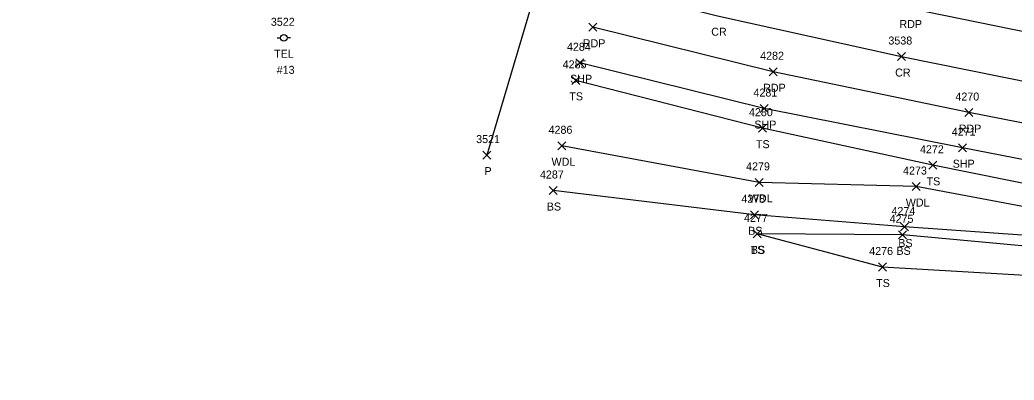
# Model space of a CAD drawing. Extents: x 1647574 to 1652703, y 212895 to 228670.
# Drawn here: x 1648648 to 1648896.4, y 227078.5 to 227168.5 of the extents above; entities that cross this region are included whole.
import ezdxf

# ---------------------------------------------------------------- set-up
doc = ezdxf.new("R2010")
doc.units = 0
for name, color, linetype in [('D_A', 7, 'Continuous'), ('D_I', 7, 'Continuous'), ('D_TIC', 7, 'Continuous'), ('DCP', 7, 'Continuous'), ('L_A', 7, 'Continuous'), ('L_I', 7, 'Continuous'), ('L_TIC', 7, 'Continuous'), ('LAWA', 7, 'Continuous'), ('LELB', 7, 'Continuous'), ('P_A', 7, 'Continuous'), ('P_I', 7, 'Continuous'), ('P_TIC', 7, 'Continuous'), ('PET', 7, 'Continuous'), ('PRC', 7, 'Continuous'), ('PSP', 7, 'Continuous'), ('U_A', 7, 'Continuous'), ('U_C', 7, 'Continuous'), ('U_I', 7, 'Continuous'), ('UP', 7, 'Continuous')]:
    doc.layers.add(name, color=color, linetype=linetype)

msp = doc.modelspace()

# ---------------------------------------------------------------- linework, layer by layer
at = {"layer": 'D_TIC'}
for points in [[(1648763.66, 227133.75), (1648765.66, 227135.75)], [(1648765.66, 227133.75), (1648763.66, 227135.75)]]:
    msp.add_lwpolyline(points, dxfattribs=at)
at = {"layer": 'DCP'}
msp.add_lwpolyline([(1648791.3, 227224.56), (1648764.66, 227134.75)], dxfattribs=at)
at = {"layer": 'L_TIC'}
for points in [[(1648785.83, 227152.43), (1648787.83, 227154.43)], [(1648787.83, 227152.43), (1648785.83, 227154.43)], [(1648832.46, 227140.48), (1648834.46, 227142.48)], [(1648834.46, 227140.48), (1648832.46, 227142.48)], [(1648782.37, 227136.08), (1648784.37, 227138.08)], [(1648784.37, 227136.08), (1648782.37, 227138.08)], [(1648875.09, 227131.2), (1648877.09, 227133.2)], [(1648877.09, 227131.2), (1648875.09, 227133.2)], [(1648831.67, 227126.94), (1648833.67, 227128.94)], [(1648833.67, 227126.94), (1648831.67, 227128.94)], [(1648870.87, 227125.89), (1648872.87, 227127.89)], [(1648872.87, 227125.89), (1648870.87, 227127.89)], [(1648780.16, 227124.9), (1648782.16, 227126.9)], [(1648782.16, 227124.9), (1648780.16, 227126.9)], [(1648830.48, 227118.83), (1648832.48, 227120.83)], [(1648832.48, 227118.83), (1648830.48, 227120.83)], [(1648867.98, 227115.79), (1648869.98, 227117.79)], [(1648869.98, 227115.79), (1648867.98, 227117.79)], [(1648831.14, 227114.07), (1648833.14, 227116.07)], [(1648833.14, 227114.07), (1648831.14, 227116.07)], [(1648831.14, 227114.07), (1648833.14, 227116.07)], [(1648833.14, 227114.07), (1648831.14, 227116.07)], [(1648867.51, 227113.83), (1648869.51, 227115.83)], [(1648869.51, 227113.83), (1648867.51, 227115.83)], [(1648862.48, 227105.79), (1648864.48, 227107.79)], [(1648864.48, 227105.79), (1648862.48, 227107.79)]]:
    msp.add_lwpolyline(points, dxfattribs=at)
at = {"layer": 'LAWA'}
msp.add_lwpolyline([(1649030.64, 227023.85), (1649020.98, 227035.14), (1648998.91, 227050.08), (1648974.89, 227082.83), (1648958.09, 227100.96), (1648932, 227102.73), (1648925.38, 227109.58), (1648919.51, 227113.25), (1648913.13, 227119.19), (1648871.87, 227126.89), (1648832.67, 227127.94), (1648783.37, 227137.08)], dxfattribs=at)
at = {"layer": 'LELB'}
for points in [[(1649303.94, 227051.18), (1649261.07, 227060.39), (1649216.61, 227069.45), (1649178.25, 227076.12), (1649140.52, 227081.32), (1649094.47, 227090.06), (1649051.01, 227097.65), (1649006.72, 227103.93), (1648958.76, 227112.58), (1648914.48, 227124.45), (1648876.09, 227132.2), (1648833.46, 227141.48), (1648786.83, 227153.43)], [(1649303.06, 227047.28), (1649260.98, 227055.31), (1649217.96, 227064.4), (1649177.85, 227072.42), (1649139.31, 227077.28), (1649094.12, 227086.64), (1649050.12, 227095.02), (1649005.65, 227100.61), (1648959.22, 227107.57), (1648919.51, 227113.25), (1648868.98, 227116.79), (1648831.48, 227119.83), (1648781.16, 227125.9)], [(1649302.97, 227044.78), (1649260.67, 227052.98), (1649215.1, 227059.72), (1649174.92, 227066.32), (1649138.43, 227073.45), (1649092.93, 227081.32), (1649048.99, 227090.42), (1649005.13, 227098.96), (1648958.86, 227104.77), (1648925.38, 227109.58), (1648868.51, 227114.83), (1648832.14, 227115.07)], [(1648932, 227102.73), (1648863.48, 227106.79), (1648832.14, 227115.07)]]:
    msp.add_lwpolyline(points, dxfattribs=at)
at = {"layer": 'P_TIC'}
for points in [[(1648790.11, 227165.69), (1648792.11, 227167.69)], [(1648792.11, 227165.69), (1648790.11, 227167.69)], [(1648867.21, 227158.38), (1648869.21, 227160.38)], [(1648869.21, 227158.38), (1648867.21, 227160.38)], [(1648786.9, 227156.82), (1648788.9, 227158.82)], [(1648788.9, 227156.82), (1648786.9, 227158.82)], [(1648835.17, 227154.58), (1648837.17, 227156.58)], [(1648837.17, 227154.58), (1648835.17, 227156.58)], [(1648832.93, 227145.38), (1648834.93, 227147.38)], [(1648834.93, 227145.38), (1648832.93, 227147.38)], [(1648884.03, 227144.38), (1648886.03, 227146.38)], [(1648886.03, 227144.38), (1648884.03, 227146.38)], [(1648882.47, 227135.6), (1648884.47, 227137.6)], [(1648884.47, 227135.6), (1648882.47, 227137.6)]]:
    msp.add_lwpolyline(points, dxfattribs=at)
at = {"layer": 'PET'}
for points in [[(1648582.82, 227256.08), (1648618.15, 227243), (1648661.46, 227228.08), (1648697.31, 227216.44), (1648732, 227205.65), (1648767.28, 227195.85), (1648794.92, 227188.71), (1648824.66, 227181.32), (1648870.23, 227171.5), (1648904.55, 227164.5), (1648941.4, 227157.32), (1648982.59, 227149.56), (1649013.45, 227143.77), (1649051.48, 227136.02), (1649092.56, 227128.28), (1649129.41, 227121.26), (1649164.13, 227114.97), (1649203.07, 227107.32), (1649253.12, 227097.95), (1649285.33, 227091.53), (1649309.81, 227086.86)], [(1649306.68, 227064.13), (1649262.99, 227072.36), (1649217.79, 227081.09), (1649180.88, 227089.3), (1649143.91, 227096.66), (1649097.06, 227105.07), (1649054.53, 227112.89), (1649010.67, 227121.22), (1648964.11, 227130.39), (1648922.42, 227138.03), (1648885.03, 227145.38), (1648836.17, 227155.58), (1648791.11, 227166.69)]]:
    msp.add_lwpolyline(points, dxfattribs=at)
at = {"layer": 'PRC'}
msp.add_lwpolyline([(1648578.47, 227245.09), (1648614.14, 227232.38), (1648658.38, 227217.21), (1648693.17, 227205.45), (1648728.77, 227194.61), (1648764.16, 227184.6), (1648791.48, 227177.33), (1648822.26, 227169.58), (1648868.21, 227159.38), (1648902.01, 227152.53), (1648938.68, 227144.92), (1648979.68, 227137.48), (1649011.64, 227131.5), (1649049.01, 227124.37), (1649090.36, 227116.95), (1649126.94, 227110.35), (1649164.15, 227103.49), (1649199.47, 227096.77), (1649251.63, 227086.36), (1649284.28, 227080.21), (1649307.76, 227075.6)], dxfattribs=at)
at = {"layer": 'PSP'}
msp.add_lwpolyline([(1649305.23, 227055.05), (1649261.49, 227063.44), (1649216.57, 227072.89), (1649179.12, 227080.23), (1649141.32, 227088.23), (1649095.57, 227096.47), (1649052.89, 227104.28), (1649009.15, 227112.65), (1648960.8, 227122.11), (1648921.9, 227129.09), (1648883.47, 227136.6), (1648833.93, 227146.38), (1648787.9, 227157.82)], dxfattribs=at)
at = {"layer": 'UP'}
for p, q in [((1648712.27, 227164.06), (1648713.1, 227164.06)), ((1648713.93, 227164.06), (1648713.93, 227164.06)), ((1648715.6, 227164.06), (1648714.77, 227164.06)), ((1648714.77, 227164.06), (1648714.77, 227164.06)), ((1648715.6, 227164.06), (1648715.6, 227164.06))]:
    msp.add_line(p, q, dxfattribs=at)
msp.add_circle((1648713.93, 227164.06), 0.833, dxfattribs=at)

# ---------------------------------------------------------------- texts
at = {"layer": 'D_A'}
msp.add_text('P', height=2, dxfattribs=at).set_placement((1648764.03, 227129.75))
at = {"layer": 'D_I'}
msp.add_text('3521', height=2, dxfattribs=at).set_placement((1648761.96, 227137.75))
at = {"layer": 'L_A'}
for s, p in [('TS', (1648785.24, 227148.43)), ('TS', (1648831.87, 227136.48)), ('WDL', (1648780.79, 227132.08)), ('TS', (1648874.5, 227127.2)), ('WDL', (1648830.08, 227122.94)), ('BS', (1648779.6, 227120.9)), ('WDL', (1648869.29, 227121.89)), ('BS', (1648829.92, 227114.83)), ('BS', (1648867.42, 227111.79)), ('TS', (1648830.55, 227110.07)), ('BS', (1648830.58, 227110.07)), ('BS', (1648866.95, 227109.83)), ('TS', (1648861.89, 227101.79))]:
    msp.add_text(s, height=2, dxfattribs=at).set_placement(p)
at = {"layer": 'L_I'}
for s, p in [('4285', (1648783.57, 227156.43)), ('4280', (1648830.11, 227144.48)), ('4286', (1648780.05, 227140.08)), ('4272', (1648872.83, 227135.2)), ('4279', (1648829.4, 227130.94)), ('4287', (1648777.9, 227128.9)), ('4273', (1648868.61, 227129.89)), ('4278', (1648828.22, 227122.83)), ('4277', (1648828.88, 227118.07)), ('4277', (1648828.88, 227118.07)), ('4275', (1648865.25, 227117.83)), ('4274', (1648865.72, 227119.79)), ('4276', (1648860.16, 227109.79))]:
    msp.add_text(s, height=2, dxfattribs=at).set_placement(p)
at = {"layer": 'P_A'}
for s, p in [('RDP', (1648867.71, 227166.5)), ('CR', (1648820.69, 227164.58)), ('RDP', (1648788.6, 227161.69)), ('SHP', (1648785.44, 227152.82)), ('CR', (1648866.64, 227154.38)), ('RDP', (1648833.66, 227150.58)), ('SHP', (1648831.47, 227141.38)), ('RDP', (1648882.52, 227140.38)), ('SHP', (1648881.01, 227131.6))]:
    msp.add_text(s, height=2, dxfattribs=at).set_placement(p)
at = {"layer": 'P_I'}
for s, p in [('3538', (1648864.95, 227162.38)), ('4284', (1648784.64, 227160.82)), ('4282', (1648832.91, 227158.58)), ('4281', (1648831.24, 227149.38)), ('4270', (1648881.69, 227148.38)), ('4271', (1648880.78, 227139.6))]:
    msp.add_text(s, height=2, dxfattribs=at).set_placement(p)
at = {"layer": 'U_A'}
msp.add_text('TEL', height=2, dxfattribs=at).set_placement((1648711.49, 227159.06))
at = {"layer": 'U_C'}
msp.add_text('#13', height=2, dxfattribs=at).set_placement((1648712.14, 227155.06))
at = {"layer": 'U_I'}
msp.add_text('3522', height=2, dxfattribs=at).set_placement((1648710.67, 227167.06))

doc.saveas('drawing.dxf')
